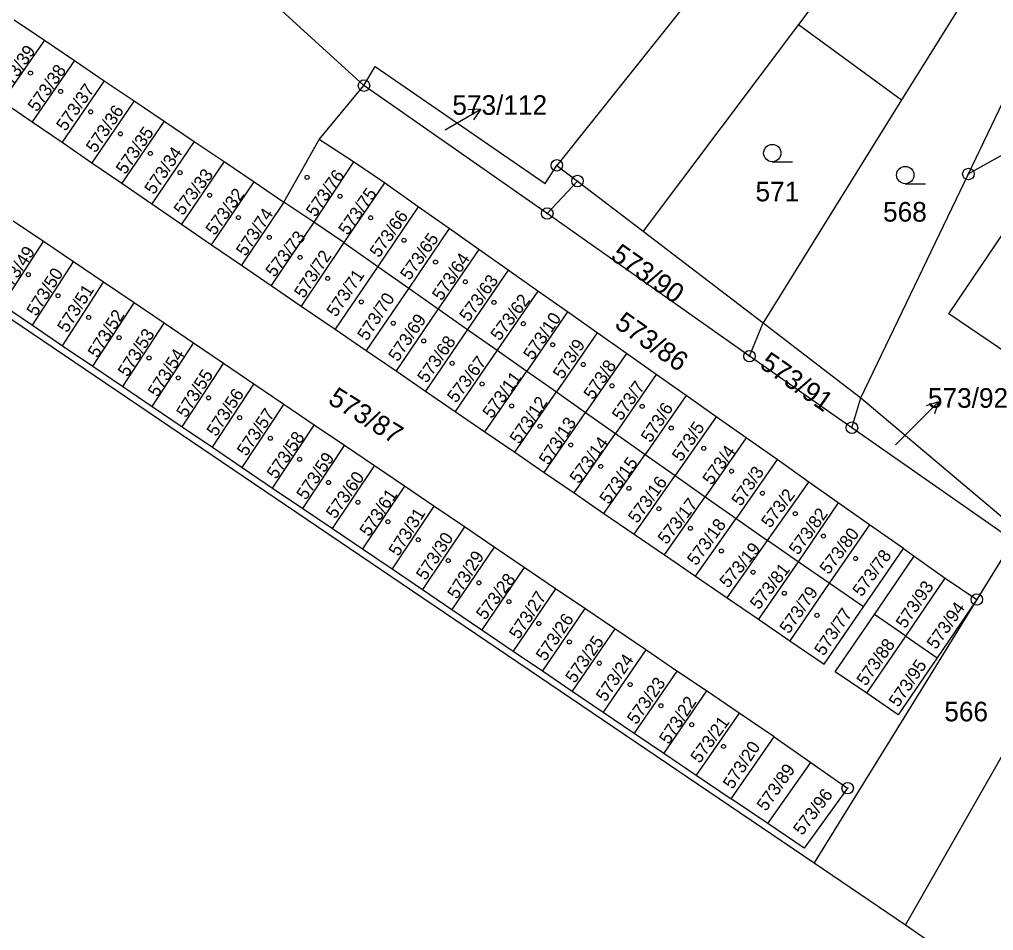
# Model space of a CAD drawing. Extents: x -776606 to -776076, y -974328 to -973875.
# Drawn here: x -776421.1 to -776336.7, y -974076.7 to -973997.7 of the extents above; entities that cross this region are included whole.
import ezdxf

# ---------------------------------------------------------------- set-up
doc = ezdxf.new("R2010")
doc.units = 0
for name, color, linetype in [('Hranice parcel', 7, 'Continuous'), ('Parcelní čísla', 7, 'Continuous'), ('Pop  PČ popisy', 7, 'Continuous'), ('Značky bodu BP', 7, 'Continuous'), ('Značky budov', 7, 'Continuous'), ('Značky kultur', 7, 'Continuous')]:
    doc.layers.add(name, color=color, linetype=linetype)

msp = doc.modelspace()

# ---------------------------------------------------------------- linework, layer by layer
at = {"layer": 'Hranice parcel'}
for p, q in [((-776391.25, -974003.46), (-776398.4, -973996.95)), ((-776421.58, -973997.75), (-776418.96, -973999.52)), ((-776353.58, -973998.16), (-776367.05, -974016.08)), ((-776353.58, -973998.16), (-776344.63, -974004.7)), ((-776418.96, -973999.52), (-776422.61, -974004.82)), ((-776418.96, -973999.52), (-776416.36, -974001.27)), ((-776416.36, -974001.27), (-776420.02, -974006.59)), ((-776416.36, -974001.27), (-776413.77, -974003.03)), ((-776413.77, -974003.03), (-776417.43, -974008.37)), ((-776413.77, -974003.03), (-776411.17, -974004.78)), ((-776395.13, -974008.13), (-776391.25, -974003.46)), ((-776375.36, -974014.55), (-776391.25, -974003.46)), ((-776411.17, -974004.78), (-776414.84, -974010.14)), ((-776411.17, -974004.78), (-776408.57, -974006.53)), ((-776344.63, -974004.7), (-776356.65, -974024.04)), ((-776338.84, -974011.12), (-776335.5, -974004.17)), ((-776422.61, -974004.82), (-776420.02, -974006.59)), ((-776420.02, -974006.59), (-776417.43, -974008.37)), ((-776408.57, -974006.53), (-776412.25, -974011.92)), ((-776408.57, -974006.53), (-776405.98, -974008.29)), ((-776398.19, -974013.55), (-776395.13, -974008.13)), ((-776392.17, -974010.07), (-776395.13, -974008.13)), ((-776332.85, -974007.77), (-776338.84, -974011.12)), ((-776417.43, -974008.37), (-776414.84, -974010.14)), ((-776405.98, -974008.29), (-776409.65, -974013.7)), ((-776405.98, -974008.29), (-776403.38, -974010.04)), ((-776414.84, -974010.14), (-776412.25, -974011.92)), ((-776403.38, -974010.04), (-776407.06, -974015.47)), ((-776403.38, -974010.04), (-776400.78, -974011.8)), ((-776392.17, -974010.07), (-776395.59, -974015.3)), ((-776389.48, -974011.9), (-776392.17, -974010.07)), ((-776374.53, -974010.37), (-776372.74, -974011.73)), ((-776348.16, -974030.54), (-776338.84, -974011.12)), ((-776412.25, -974011.92), (-776409.65, -974013.7)), ((-776404.47, -974017.25), (-776400.78, -974011.8)), ((-776400.78, -974011.8), (-776398.19, -974013.55)), ((-776389.48, -974011.9), (-776392.99, -974017.06)), ((-776386.55, -974013.97), (-776389.48, -974011.9)), ((-776372.74, -974011.73), (-776375.36, -974014.55)), ((-776372.74, -974011.73), (-776367.05, -974016.08)), ((-776409.65, -974013.7), (-776407.06, -974015.47)), ((-776398.19, -974013.55), (-776401.88, -974019.02)), ((-776395.59, -974015.3), (-776398.19, -974013.55)), ((-776386.55, -974013.97), (-776390.05, -974019.13)), ((-776383.87, -974015.86), (-776386.55, -974013.97)), ((-776357.82, -974026.92), (-776375.36, -974014.55)), ((-776419.05, -974016.97), (-776421.66, -974015.2)), ((-776407.06, -974015.47), (-776404.47, -974017.25)), ((-776395.59, -974015.3), (-776399.29, -974020.8)), ((-776392.99, -974017.06), (-776395.59, -974015.3)), ((-776383.87, -974015.86), (-776387.37, -974021.01)), ((-776381.29, -974017.67), (-776383.87, -974015.86)), ((-776367.05, -974016.08), (-776356.65, -974024.04)), ((-776422.6, -974022.48), (-776419.05, -974016.97)), ((-776416.44, -974018.74), (-776419.05, -974016.97)), ((-776404.47, -974017.25), (-776401.88, -974019.02)), ((-776392.99, -974017.06), (-776396.69, -974022.57)), ((-776392.99, -974017.06), (-776390.05, -974019.13)), ((-776381.29, -974017.67), (-776384.81, -974022.82)), ((-776378.74, -974019.46), (-776381.29, -974017.67)), ((-776420, -974024.24), (-776416.44, -974018.74)), ((-776413.83, -974020.51), (-776416.44, -974018.74)), ((-776401.88, -974019.02), (-776399.29, -974020.8)), ((-776390.05, -974019.13), (-776393.75, -974024.59)), ((-776390.05, -974019.13), (-776387.37, -974021.01)), ((-776378.74, -974019.46), (-776382.26, -974024.61)), ((-776376.18, -974021.27), (-776378.74, -974019.46)), ((-776417.39, -974026.01), (-776413.83, -974020.51)), ((-776411.19, -974022.3), (-776413.83, -974020.51)), ((-776399.29, -974020.8), (-776396.69, -974022.57)), ((-776387.37, -974021.01), (-776391.06, -974026.43)), ((-776387.37, -974021.01), (-776384.81, -974022.82)), ((-776376.18, -974021.27), (-776379.71, -974026.41)), ((-776373.61, -974023.08), (-776376.18, -974021.27)), ((-776422.6, -974022.48), (-776420, -974024.24)), ((-776414.76, -974027.79), (-776411.19, -974022.3)), ((-776408.59, -974024.06), (-776411.19, -974022.3)), ((-776396.69, -974022.57), (-776393.75, -974024.59)), ((-776384.81, -974022.82), (-776388.47, -974028.2)), ((-776384.81, -974022.82), (-776382.26, -974024.61)), ((-776373.61, -974023.08), (-776377.14, -974028.21)), ((-776371.04, -974024.89), (-776373.61, -974023.08)), ((-776420, -974024.24), (-776417.39, -974026.01)), ((-776412.17, -974029.55), (-776408.59, -974024.06)), ((-776406.03, -974025.79), (-776408.59, -974024.06)), ((-776357.82, -974026.92), (-776356.65, -974024.04)), ((-776356.65, -974024.04), (-776348.16, -974030.54)), ((-776393.75, -974024.59), (-776391.06, -974026.43)), ((-776382.26, -974024.61), (-776385.91, -974029.95)), ((-776382.26, -974024.61), (-776379.71, -974026.41)), ((-776371.04, -974024.89), (-776374.57, -974030.02)), ((-776368.49, -974026.69), (-776371.04, -974024.89)), ((-776409.62, -974031.27), (-776406.03, -974025.79)), ((-776403.43, -974027.56), (-776406.03, -974025.79)), ((-776417.39, -974026.01), (-776414.76, -974027.79)), ((-776391.06, -974026.43), (-776388.47, -974028.2)), ((-776379.71, -974026.41), (-776383.35, -974031.71)), ((-776379.71, -974026.41), (-776377.14, -974028.21)), ((-776368.49, -974026.69), (-776372.03, -974031.81)), ((-776365.9, -974028.51), (-776368.49, -974026.69)), ((-776407.02, -974033.03), (-776403.43, -974027.56)), ((-776400.79, -974029.35), (-776403.43, -974027.56)), ((-776348.94, -974033.12), (-776357.82, -974026.92)), ((-776414.76, -974027.79), (-776412.17, -974029.55)), ((-776388.47, -974028.2), (-776385.91, -974029.95)), ((-776380.76, -974033.48), (-776377.14, -974028.21)), ((-776377.14, -974028.21), (-776374.57, -974030.02)), ((-776365.9, -974028.51), (-776369.45, -974033.62)), ((-776363.32, -974030.33), (-776365.9, -974028.51)), ((-776412.17, -974029.55), (-776409.62, -974031.27)), ((-776404.39, -974034.82), (-776400.79, -974029.35)), ((-776398.19, -974031.11), (-776400.79, -974029.35)), ((-776385.91, -974029.95), (-776383.35, -974031.71)), ((-776378.18, -974035.25), (-776374.57, -974030.02)), ((-776374.57, -974030.02), (-776372.03, -974031.81)), ((-776363.32, -974030.33), (-776366.88, -974035.44)), ((-776360.71, -974032.17), (-776363.32, -974030.33)), ((-776348.94, -974033.12), (-776348.16, -974030.54)), ((-776348.16, -974030.54), (-776334.46, -974042.11)), ((-776409.62, -974031.27), (-776407.02, -974033.03)), ((-776401.8, -974036.57), (-776398.19, -974031.11)), ((-776395.56, -974032.89), (-776398.19, -974031.11)), ((-776383.35, -974031.71), (-776380.76, -974033.48)), ((-776375.62, -974037), (-776372.03, -974031.81)), ((-776372.03, -974031.81), (-776369.45, -974033.62)), ((-776360.71, -974032.17), (-776364.27, -974037.27)), ((-776358.1, -974034), (-776360.71, -974032.17)), ((-776407.02, -974033.03), (-776404.39, -974034.82)), ((-776399.18, -974038.35), (-776395.56, -974032.89)), ((-776392.94, -974034.67), (-776395.56, -974032.89)), ((-776380.76, -974033.48), (-776378.18, -974035.25)), ((-776334.96, -974042.91), (-776348.94, -974033.12)), ((-776373.03, -974038.78), (-776369.45, -974033.62)), ((-776369.45, -974033.62), (-776366.88, -974035.44)), ((-776358.1, -974034), (-776361.67, -974039.1)), ((-776355.42, -974035.89), (-776358.1, -974034)), ((-776404.39, -974034.82), (-776401.8, -974036.57)), ((-776396.56, -974040.12), (-776392.94, -974034.67)), ((-776390.35, -974036.43), (-776392.94, -974034.67)), ((-776378.18, -974035.25), (-776375.62, -974037)), ((-776370.44, -974040.55), (-776366.88, -974035.44)), ((-776366.88, -974035.44), (-776364.27, -974037.27)), ((-776355.42, -974035.89), (-776358.99, -974040.98)), ((-776352.67, -974037.83), (-776355.42, -974035.89)), ((-776401.8, -974036.57), (-776399.18, -974038.35)), ((-776393.98, -974041.87), (-776390.35, -974036.43)), ((-776387.74, -974038.19), (-776390.35, -974036.43)), ((-776375.62, -974037), (-776373.03, -974038.78)), ((-776367.81, -974042.35), (-776364.27, -974037.27)), ((-776364.27, -974037.27), (-776361.67, -974039.1)), ((-776399.18, -974038.35), (-776396.56, -974040.12)), ((-776387.74, -974038.19), (-776391.38, -974043.63)), ((-776385.18, -974039.93), (-776387.74, -974038.19)), ((-776356.25, -974042.91), (-776352.67, -974037.83)), ((-776350.12, -974039.63), (-776352.67, -974037.83)), ((-776373.03, -974038.78), (-776370.44, -974040.55)), ((-776365.2, -974044.14), (-776361.67, -974039.1)), ((-776361.67, -974039.1), (-776358.99, -974040.98)), ((-776396.56, -974040.12), (-776393.98, -974041.87)), ((-776385.18, -974039.93), (-776388.82, -974045.37)), ((-776382.54, -974041.72), (-776385.18, -974039.93)), ((-776350.12, -974039.63), (-776353.61, -974044.74)), ((-776347.42, -974041.53), (-776350.12, -974039.63)), ((-776370.44, -974040.55), (-776367.81, -974042.35)), ((-776362.5, -974045.99), (-776358.99, -974040.98)), ((-776358.99, -974040.98), (-776356.25, -974042.91)), ((-776393.98, -974041.87), (-776391.38, -974043.63)), ((-776382.54, -974041.72), (-776386.19, -974047.15)), ((-776379.97, -974043.47), (-776382.54, -974041.72)), ((-776347.42, -974041.53), (-776350.9, -974046.61)), ((-776344.48, -974043.6), (-776347.42, -974041.53)), ((-776367.81, -974042.35), (-776365.2, -974044.14)), ((-776391.38, -974043.63), (-776388.82, -974045.37)), ((-776379.97, -974043.47), (-776383.62, -974048.89)), ((-776377.37, -974045.23), (-776379.97, -974043.47)), ((-776359.75, -974047.87), (-776356.25, -974042.91)), ((-776353.61, -974044.74), (-776356.25, -974042.91)), ((-776347.94, -974048.65), (-776344.48, -974043.6)), ((-776344.48, -974043.6), (-776343.54, -974044.26)), ((-776334.96, -974042.91), (-776338.11, -974048.02)), ((-776365.2, -974044.14), (-776362.5, -974045.99)), ((-776346.99, -974049.31), (-776343.54, -974044.26)), ((-776343.54, -974044.26), (-776340.85, -974046.16)), ((-776377.37, -974045.23), (-776381.03, -974050.64)), ((-776374.64, -974047.08), (-776377.37, -974045.23)), ((-776353.61, -974044.74), (-776357.03, -974049.73)), ((-776350.9, -974046.61), (-776353.61, -974044.74)), ((-776388.82, -974045.37), (-776386.19, -974047.15)), ((-776362.5, -974045.99), (-776359.75, -974047.87)), ((-776344.27, -974051.19), (-776340.85, -974046.16)), ((-776340.85, -974046.16), (-776338.11, -974048.02)), ((-776350.9, -974046.61), (-776354.31, -974051.59)), ((-776347.94, -974048.65), (-776350.9, -974046.61)), ((-776386.19, -974047.15), (-776383.62, -974048.89)), ((-776374.64, -974047.08), (-776378.31, -974052.49)), ((-776372.1, -974048.8), (-776374.64, -974047.08)), ((-776359.75, -974047.87), (-776357.03, -974049.73)), ((-776338.11, -974048.02), (-776344.68, -974058.65)), ((-776338.11, -974048.02), (-776341.55, -974053.07)), ((-776383.62, -974048.89), (-776381.03, -974050.64)), ((-776372.1, -974048.8), (-776375.78, -974054.2)), ((-776369.5, -974050.56), (-776372.1, -974048.8)), ((-776344.27, -974051.19), (-776346.99, -974049.31)), ((-776357.03, -974049.73), (-776354.31, -974051.59)), ((-776381.03, -974050.64), (-776378.31, -974052.49)), ((-776369.5, -974050.56), (-776373.19, -974055.96)), ((-776366.8, -974052.39), (-776369.5, -974050.56)), ((-776347.66, -974056.15), (-776344.27, -974051.19)), ((-776344.27, -974051.19), (-776341.55, -974053.07)), ((-776378.31, -974052.49), (-776375.78, -974054.2)), ((-776366.8, -974052.39), (-776370.5, -974057.78)), ((-776364.11, -974054.22), (-776366.8, -974052.39)), ((-776375.78, -974054.2), (-776373.19, -974055.96)), ((-776364.11, -974054.22), (-776367.81, -974059.6)), ((-776361.55, -974055.95), (-776364.11, -974054.22)), ((-776373.19, -974055.96), (-776370.5, -974057.78)), ((-776361.55, -974055.95), (-776365.26, -974061.33)), ((-776358.73, -974057.86), (-776361.55, -974055.95)), ((-776370.5, -974057.78), (-776367.81, -974059.6)), ((-776358.73, -974057.86), (-776362.45, -974063.24)), ((-776355.67, -974059.93), (-776358.73, -974057.86)), ((-776344.68, -974058.65), (-776352.22, -974070.86)), ((-776367.81, -974059.6), (-776365.26, -974061.33)), ((-776334.7, -974059.4), (-776344.3, -974076.22)), ((-776359.4, -974065.3), (-776355.67, -974059.93)), ((-776355.67, -974059.93), (-776352.49, -974062.15)), ((-776365.26, -974061.33), (-776362.45, -974063.24)), ((-776356.23, -974067.44), (-776352.49, -974062.15)), ((-776362.45, -974063.24), (-776359.4, -974065.3)), ((-776356.23, -974067.44), (-776359.4, -974065.3)), ((-776352.22, -974070.86), (-776344.3, -974076.22)), ((-776344.3, -974076.22), (-776331.9, -974084.75))]:
    msp.add_line(p, q, dxfattribs=at)
for points in [[(-776337.75, -973970.3), (-776338.32, -973970.69), (-776348.3, -973977.53), (-776374.53, -974010.37)], [(-776342.98, -973985.31), (-776344.9, -973986.62), (-776353.58, -973998.16)], [(-776336.89, -973994.45), (-776339.24, -973996.03), (-776344.63, -974004.7)], [(-776437.4, -973999.42), (-776442.93, -974009.42), (-776352.22, -974070.86)], [(-776391.25, -974003.46), (-776390.27, -974001.8), (-776375.54, -974011.94), (-776374.53, -974010.37)], [(-776340.54, -974023.25), (-776332.99, -974012.08), (-776329.69, -974014.3), (-776328.36, -974015.19), (-776329.75, -974017.28), (-776324.86, -974020.59), (-776331.02, -974029.69), (-776340.54, -974023.25)], [(-776354.31, -974051.59), (-776351.34, -974053.63), (-776347.94, -974048.65)], [(-776347.66, -974056.15), (-776350.39, -974054.28), (-776346.99, -974049.31)], [(-776341.55, -974053.07), (-776344.92, -974058.03), (-776347.66, -974056.15)], [(-776352.49, -974062.15), (-776349.31, -974064.37), (-776353.07, -974069.58), (-776356.23, -974067.44)]]:
    msp.add_lwpolyline(points, dxfattribs=at)
at = {"layer": 'Pop  PČ popisy'}
for p, q in [((-776383.73, -974007), (-776381.131, -974005.5)), ((-776381.131, -974005.5), (-776382.249, -974005.567)), ((-776381.131, -974005.5), (-776381.748, -974006.434)), ((-776384.22, -974007.28), (-776383.73, -974007)), ((-776343.55, -974032.99), (-776341.428, -974030.868)), ((-776341.428, -974030.868), (-776342.49, -974031.222)), ((-776341.428, -974030.868), (-776341.782, -974031.93)), ((-776345.16, -974034.6), (-776343.55, -974032.99))]:
    msp.add_line(p, q, dxfattribs=at)
at = {"layer": 'Značky bodu BP'}
for centre, radius in [((-776391.25, -974003.46), 0.5), ((-776391.25, -974003.46), 0.0303), ((-776374.53, -974010.37), 0.5), ((-776374.53, -974010.37), 0.0303), ((-776338.84, -974011.12), 0.5), ((-776372.74, -974011.73), 0.5), ((-776338.84, -974011.12), 0.0303), ((-776372.74, -974011.73), 0.0303), ((-776375.36, -974014.55), 0.5), ((-776375.36, -974014.55), 0.0303), ((-776357.82, -974026.92), 0.5), ((-776357.82, -974026.92), 0.0303), ((-776348.94, -974033.12), 0.5), ((-776348.94, -974033.12), 0.0303), ((-776338.11, -974048.02), 0.5), ((-776338.11, -974048.02), 0.0303), ((-776349.31, -974064.37), 0.5), ((-776349.31, -974064.37), 0.0303)]:
    msp.add_circle(centre, radius, dxfattribs=at)
at = {"layer": 'Značky budov'}
for centre in [(-776420.167, -974002.369), (-776417.557, -974003.959), (-776414.957, -974005.729), (-776412.367, -974007.639), (-776409.777, -974009.339), (-776407.197, -974010.999), (-776396.187, -974011.409), (-776404.637, -974012.959), (-776393.327, -974013.049), (-776402.137, -974014.899), (-776390.677, -974014.919), (-776399.467, -974016.619), (-776387.777, -974016.869), (-776396.787, -974018.349), (-776385.047, -974018.759), (-776420.357, -974019.849), (-776394.397, -974020.179), (-776382.457, -974020.469), (-776417.777, -974021.679), (-776391.477, -974022.209), (-776379.977, -974022.259), (-776415.117, -974023.559), (-776388.707, -974024.059), (-776377.427, -974024.109), (-776412.487, -974025.309), (-776386.067, -974025.599), (-776374.887, -974025.929), (-776409.887, -974027.069), (-776383.607, -974027.539), (-776372.237, -974027.639), (-776407.357, -974028.799), (-776381.007, -974029.329), (-776369.747, -974029.489), (-776404.727, -974030.529), (-776378.447, -974031.229), (-776367.127, -974031.269), (-776402.037, -974032.249), (-776375.987, -974032.989), (-776364.607, -974033.149), (-776399.367, -974034.039), (-776373.317, -974034.609), (-776361.787, -974034.909), (-776396.837, -974035.859), (-776370.717, -974036.479), (-776359.377, -974036.889), (-776394.327, -974037.869), (-776368.277, -974038.369), (-776391.777, -974039.579), (-776356.697, -974038.799), (-776365.677, -974040.149), (-776389.177, -974041.269), (-776353.857, -974040.579), (-776362.947, -974041.839), (-776386.547, -974042.839), (-776351.407, -974042.519), (-776360.257, -974043.809), (-776383.947, -974044.639), (-776348.627, -974044.459), (-776357.507, -974045.649), (-776381.287, -974046.569), (-776354.807, -974047.479), (-776378.687, -974048.199), (-776351.967, -974049.389), (-776376.087, -974050.099), (-776373.437, -974051.699), (-776370.847, -974053.539), (-776368.167, -974055.389), (-776365.497, -974057.229), (-776362.827, -974058.869), (-776360.077, -974060.759)]:
    msp.add_circle(centre, 0.175, dxfattribs=at)
at = {"layer": 'Značky kultur'}
for p, q in [((-776355.843, -974010.06), (-776354.093, -974010.06)), ((-776344.313, -974011.96), (-776342.563, -974011.96))]:
    msp.add_line(p, q, dxfattribs=at)
for centre in [(-776355.843, -974009.31), (-776344.313, -974011.21)]:
    msp.add_circle(centre, 0.75, dxfattribs=at)

# ---------------------------------------------------------------- texts
at = {"layer": 'Parcelní čísla'}
for s, height, rotation, p in [('573/39', 1.1, 56, (-776422.194, -974004.157)), ('573/38', 1.1, 55, (-776419.599, -974005.805)), ('573/37', 1.1, 55, (-776417.129, -974007.485)), ('573/36', 1.1, 56, (-776414.534, -974009.357)), ('573/35', 1.1, 56, (-776411.944, -974011.237)), ('573/34', 1.1, 56, (-776409.464, -974012.977)), ('573/33', 1.1, 53, (-776406.97, -974014.79)), ('573/76', 1.1, 55, (-776395.469, -974014.925)), ('573/32', 1.1, 54, (-776404.195, -974016.513)), ('573/75', 1.1, 55, (-776392.659, -974016.505)), ('573/74', 1.1, 57, (-776401.508, -974018.329)), ('573/66', 1.1, 55, (-776389.949, -974018.445)), ('573/73', 1.1, 52, (-776399.026, -974020.148)), ('573/65', 1.1, 55, (-776387.299, -974020.415)), ('573/49', 1.1, 57, (-776422.178, -974021.619)), ('573/90', 1.7, 325, (-776369.967, -974018.446)), ('573/72', 1.1, 57, (-776396.468, -974021.969)), ('573/64', 1.1, 56, (-776384.524, -974022.177)), ('573/50', 1.1, 58, (-776419.663, -974023.531)), ('573/71', 1.1, 56, (-776393.674, -974023.597)), ('573/63', 1.1, 54, (-776382.185, -974024.003)), ('573/51', 1.1, 58, (-776416.993, -974024.951)), ('573/70', 1.1, 57, (-776390.988, -974025.659)), ('573/62', 1.1, 53, (-776379.5, -974025.66)), ('573/52', 1.1, 58, (-776414.353, -974027.141)), ('573/69', 1.1, 56, (-776388.314, -974027.467)), ('573/10', 1.1, 56, (-776376.614, -974027.337)), ('573/86', 1.7, 325, (-776369.617, -974024.346)), ('573/53', 1.1, 58, (-776411.743, -974028.791)), ('573/68', 1.1, 55, (-776385.819, -974029.325)), ('573/9', 1.1, 57, (-776374.028, -974028.989)), ('573/54', 1.1, 58, (-776409.143, -974030.541)), ('573/91', 1.7, 325, (-776357.047, -974027.826)), ('573/67', 1.1, 53, (-776383.26, -974031.04)), ('573/8', 1.1, 56, (-776371.384, -974030.767)), ('573/55', 1.1, 58, (-776406.673, -974032.331)), ('573/11', 1.1, 54, (-776380.175, -974032.403)), ('573/7', 1.1, 55, (-776368.939, -974032.585)), ('573/56', 1.1, 57, (-776404.058, -974033.959)), ('573/87', 1.7, 328, (-776394.47, -974030.95)), ('573/12', 1.1, 56, (-776377.794, -974034.617)), ('573/6', 1.1, 57, (-776366.398, -974034.489)), ('573/57', 1.1, 56, (-776401.444, -974035.667)), ('573/13', 1.1, 57, (-776375.248, -974036.439)), ('573/5', 1.1, 56, (-776363.724, -974036.127)), ('573/58', 1.1, 56, (-776398.864, -974037.657)), ('573/14', 1.1, 54, (-776372.625, -974038.053)), ('573/4', 1.1, 55, (-776361.089, -974038.165)), ('573/59', 1.1, 56, (-776396.284, -974039.467)), ('573/15', 1.1, 55, (-776370.019, -974039.845)), ('573/3', 1.1, 56, (-776358.564, -974039.997)), ('573/60', 1.1, 55, (-776393.739, -974041.095)), ('573/16', 1.1, 54, (-776367.555, -974041.483)), ('573/61', 1.1, 56, (-776390.814, -974042.637)), ('573/2', 1.1, 53, (-776356.03, -974041.89)), ('573/17', 1.1, 52, (-776365.016, -974043.318)), ('573/31', 1.1, 58, (-776388.263, -974044.341)), ('573/82', 1.1, 54, (-776353.615, -974044.233)), ('573/18', 1.1, 54, (-776362.435, -974045.153)), ('573/80', 1.1, 53, (-776350.96, -974045.92)), ('573/30', 1.1, 57, (-776385.898, -974046.429)), ('573/19', 1.1, 50, (-776359.688, -974047.103)), ('573/29', 1.1, 58, (-776383.173, -974048.061)), ('573/78', 1.1, 54, (-776348.095, -974047.843)), ('573/81', 1.1, 52, (-776357.016, -974048.968)), ('573/28', 1.1, 53, (-776380.75, -974049.87)), ('573/79', 1.1, 55, (-776354.409, -974051.065)), ('573/93', 1.1, 56, (-776344.314, -974050.607)), ('573/27', 1.1, 57, (-776377.828, -974051.539)), ('573/77', 1.1, 56, (-776351.384, -974052.977)), ('573/94', 1.1, 55, (-776341.649, -974052.415)), ('573/26', 1.1, 56, (-776375.524, -974053.437)), ('573/25', 1.1, 55, (-776372.979, -974055.345)), ('573/88', 1.1, 55, (-776347.729, -974055.585)), ('573/24', 1.1, 56, (-776370.314, -974056.957)), ('573/95', 1.1, 56, (-776344.914, -974057.427)), ('573/23', 1.1, 55, (-776367.629, -974058.935)), ('573/22', 1.1, 57, (-776364.818, -974060.649)), ('573/21', 1.1, 54, (-776362.145, -974062.293)), ('573/20', 1.1, 57, (-776359.288, -974064.539)), ('573/89', 1.1, 55, (-776356.389, -974066.445)), ('573/96', 1.1, 53, (-776353.25, -974068.54))]:
    msp.add_text(s, height=height, rotation=rotation, dxfattribs=at).set_placement(p)
for s, p in [('573/112', (-776383.586, -974005.99)), ('571', (-776357.3, -974013.49)), ('568', (-776346.24, -974015.25)), ('573/92', (-776342.35, -974031.39)), ('566', (-776340.93, -974058.58))]:
    msp.add_text(s, height=1.7, dxfattribs=at).set_placement(p)

doc.saveas('drawing.dxf')
